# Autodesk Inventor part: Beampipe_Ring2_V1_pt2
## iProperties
Shininess: 64.0
Length Units: 11269
Angle Units: 11279
Time Units: 11290
Mass Units: 11283
Length Display Precision: 3
Angle Display Precision: 2
Compacted: True
Part Number: Beampipe_Ring2_V1_pt2
Document SubType Name: Modeling
Created: 2004-08
Designer: John Blackburn
Manufacturer: Standard
Standards Organization: Custom
Material: Aluminum-6061
Density: 0.0
Volumn: 0.0
Area: 0.0
PropertySet Name: Model Information
Control State: 0
Master: False
Checked Out: False
Author: John Blackburn
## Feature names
1. Extrusion1
2. Split1
3. Hole4
4. Hole5
5. Hole9
6. Hole10
7. Hole11
